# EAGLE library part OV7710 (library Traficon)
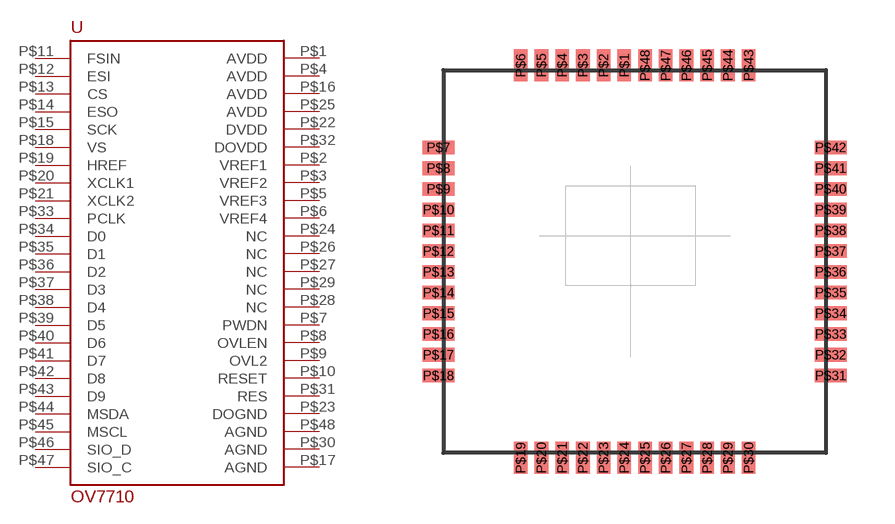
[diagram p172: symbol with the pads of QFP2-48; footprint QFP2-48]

Designator prefix U

## OV7710  [QFP2-48]
P$1  AVDD  sup
P$2  VREF1  pas
P$3  VREF2  pas
P$4  AVDD  sup
P$5  VREF3  pas
P$6  VREF4  pas
P$7  PWDN  in
P$8  OVLEN  in
P$9  OVL2  in
P$10  RESET  in
P$11  FSIN  in
P$12  ESI  in
P$13  CS  out
P$14  ESO
P$15  SCK
P$16  AVDD  sup
P$17  AGND  sup
P$18  VS  out
P$19  HREF  out
P$20  XCLK1  in
P$21  XCLK2  out
P$22  DVDD  sup
P$23  DOGND  sup
P$24  NC  nc
P$25  AVDD  sup
P$26  NC  nc
P$27  NC  nc
P$28  NC  nc
P$29  NC  nc
P$30  AGND  sup
P$31  RES  in
P$32  DOVDD  sup
P$33  PCLK  out
P$34  D0  out
P$35  D1  out
P$36  D2  out
P$37  D3  out
P$38  D4  out
P$39  D5  out
P$40  D6  out
P$41  D7  out
P$42  D8  out
P$43  D9  out
P$44  MSDA
P$45  MSCL  out
P$46  SIO_D
P$47  SIO_C  in
P$48  AGND  sup

## Footprint QFP2-48 (pad centres in mm)
smd 0.43 x 1: P$1 -0.325,6.15; P$2 -0.975,6.15; P$3 -1.625,6.15; P$4 -2.275,6.15; P$5 -2.925,6.15; P$6 -3.575,6.15; P$19 -3.575,-6.15; P$20 -2.925,-6.15; P$21 -2.275,-6.15; P$22 -1.625,-6.15; P$23 -0.975,-6.15; P$24 -0.325,-6.15; P$25 0.325,-6.15; P$26 0.975,-6.15; P$27 1.625,-6.15; P$28 2.275,-6.15; P$29 2.925,-6.15; P$30 3.575,-6.15; P$43 3.575,6.15; P$44 2.925,6.15; P$45 2.275,6.15; P$46 1.625,6.15; P$47 0.975,6.15; P$48 0.325,6.15
smd 1 x 0.43: P$7 -6.15,3.575; P$8 -6.15,2.925; P$9 -6.15,2.275; P$10 -6.15,1.625; P$11 -6.15,0.975; P$12 -6.15,0.325; P$13 -6.15,-0.325; P$14 -6.15,-0.975; P$15 -6.15,-1.625; P$16 -6.15,-2.275; P$17 -6.15,-2.925; P$18 -6.15,-3.575; P$31 6.15,-3.575; P$32 6.15,-2.925; P$33 6.15,-2.275; P$34 6.15,-1.625; P$35 6.15,-0.975; P$36 6.15,-0.325; P$37 6.15,0.325; P$38 6.15,0.975; P$39 6.15,1.625; P$40 6.15,2.275; P$41 6.15,2.925; P$42 6.15,3.575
